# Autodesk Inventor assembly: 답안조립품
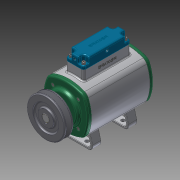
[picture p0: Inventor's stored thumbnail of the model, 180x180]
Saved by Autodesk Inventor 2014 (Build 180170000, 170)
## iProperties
Created: 2016-10
Part Number: 답안조립품
Document SubType Name: Assembly
Designer: user
Author: user
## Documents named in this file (18)
- C:\Users\user\Desktop\361008V1004\답안조립품.iam
- C:\Users\user\Desktop\361008V1004\본체.ipt
- C:\Users\user\Desktop\361008V1004\V-벨트풀리.ipt
- C:\Users\user\Desktop\361008V1004\뒷커버.ipt
- C:\Users\user\Desktop\361008V1004\멈춤나사 M4x5.ipt
- C:\Users\user\Desktop\361008V1004\베어링 6203.ipt
- C:\Users\user\Desktop\361008V1004\볼트 M4 x 12.ipt
- C:\Users\user\Desktop\361008V1004\볼트 M4 x 16.ipt
- C:\Users\user\Desktop\361008V1004\부시.ipt
- C:\Users\user\Desktop\361008V1004\스프링1.ipt
- C:\Users\user\Desktop\361008V1004\스프링2.ipt
- C:\Users\user\Desktop\361008V1004\스프링3.ipt
- C:\Users\user\Desktop\361008V1004\슬라이드.ipt
- C:\Users\user\Desktop\361008V1004\앞커버.ipt
- C:\Users\user\Desktop\361008V1004\오일실 17 30 8.ipt
- C:\Users\user\Desktop\361008V1004\축.ipt
- C:\Users\user\Desktop\361008V1004\키 - 5 x 5 x 18.ipt
- C:\Users\user\Desktop\361008V1004\헤더커버.ipt
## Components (4 placed, 3 different names)
1. V-벨트풀리:1 — Insert:7, Angle:2, Mate:1
2. 7-베어링 6203:1 — Insert:1, Insert:3
3. 헤더커버:1 — Insert:15, Insert:16, Insert:17, Insert:18, Insert:19
4. 7-베어링 6203:2 — Insert:2, Insert:4
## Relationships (12: Insert 10, Angle 1, Mate 1)
- Insert:1: 7-베어링 6203:1
- Insert:2: 7-베어링 6203:2
- Insert:3: 7-베어링 6203:1
- Insert:4: 7-베어링 6203:2
- Insert:7: V-벨트풀리:1
- Angle:2: V-벨트풀리:1
- Mate:1: V-벨트풀리:1
- Insert:15: 헤더커버:1
- Insert:16: 헤더커버:1
- Insert:17: 헤더커버:1
- Insert:18: 헤더커버:1
- Insert:19: 헤더커버:1
